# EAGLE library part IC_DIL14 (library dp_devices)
Universal 14pins IC
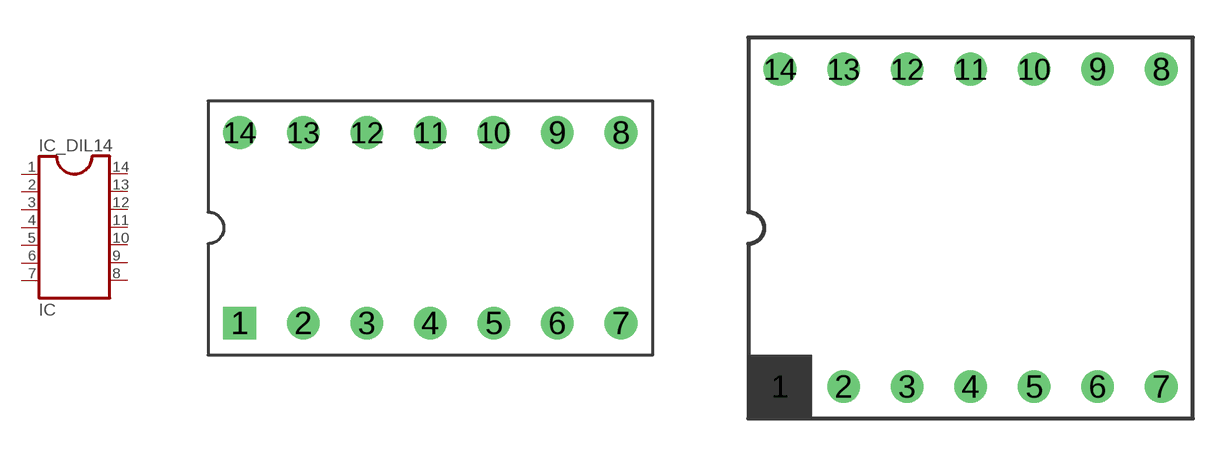
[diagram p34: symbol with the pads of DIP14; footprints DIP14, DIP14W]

Designator prefix IC

## IC_DIL14-PTH  [DIP14]
1  1
2  2
3  3
4  4
5  5
6  6
7  7
8  8
9  9
10  10
11  11
12  12
13  13
14  14

## IC_DIL14-PTHW  [DIP14W]
Pads as for DIP14

## Footprint DIP14 (pad centres in mm)
drill 0.8 square: 1 -7.62,-3.81
drill 0.8 round: 2 -5.08,-3.81; 3 -2.54,-3.81; 4 0,-3.81; 5 2.54,-3.81; 6 5.08,-3.81; 7 7.62,-3.81; 8 7.62,3.81; 9 5.08,3.81; 10 2.54,3.81; 11 0,3.81; 12 -2.54,3.81; 13 -5.08,3.81; 14 -7.62,3.81

## Footprint DIP14W (pad centres in mm)
drill 0.8 square: 1 -7.62,-6.35
drill 0.8 round: 2 -5.08,-6.35; 3 -2.54,-6.35; 4 0,-6.35; 5 2.54,-6.35; 6 5.08,-6.35; 7 7.62,-6.35; 8 7.62,6.35; 9 5.08,6.35; 10 2.54,6.35; 11 0,6.35; 12 -2.54,6.35; 13 -5.08,6.35; 14 -7.62,6.35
